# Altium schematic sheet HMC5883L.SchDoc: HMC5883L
size Letter
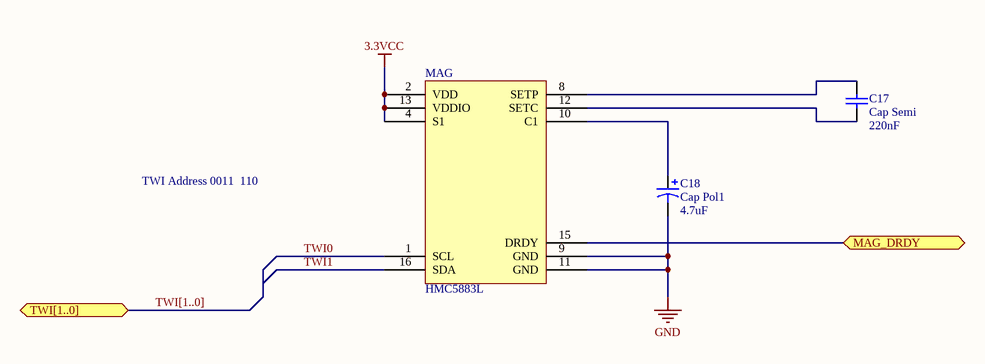
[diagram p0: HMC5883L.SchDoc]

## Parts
C17  Cap Semi  value 220nF  [CAPC2012N]
C18  Cap Pol1  value 4.7uF  [TC3528-1411]
MAG  HMC5883L  [HMC5883L - ECESHOP]

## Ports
MAG_DRDY, TWI[1..0] (bidir)

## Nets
3.3VCC: MAG.2(VDD) MAG.4(S1) MAG.13(VDDIO)
GND: C18.2 MAG.9(GND) MAG.11(GND)
MAG_DRDY: MAG.15(DRDY) ; port MAG_DRDY
TWI0: MAG.1(SCL)
TWI1: MAG.16(SDA)
NetC17_1: C17.1 MAG.8(SETP)
NetC17_2: C17.2 MAG.12(SETC)
NetC18_1: C18.1 MAG.10(C1)

Not connected (* = marked no-connect by the designer): MAG 3(NC) 5(NC) 6(NC) 7(NC) 14(NC)

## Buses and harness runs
bus TWI[1..0] = port TWI[1..0]

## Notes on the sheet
- TWI Address 0011  110

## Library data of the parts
C17 = Cap Semi: Capacitor (Semiconductor SIM Model)
C18 = Cap Pol1: Polarized Capacitor (Radial)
